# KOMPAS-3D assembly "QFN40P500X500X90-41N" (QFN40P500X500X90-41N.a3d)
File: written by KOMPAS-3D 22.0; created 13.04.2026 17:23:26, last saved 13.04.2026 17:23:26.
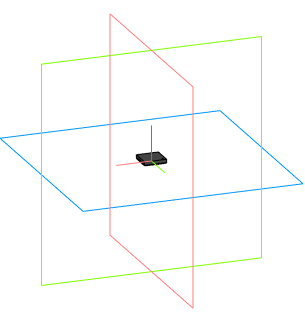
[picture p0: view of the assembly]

Document properties: Автор: Andrey; Полное имя файла: C:\Users\User1\Documents\QFN40P500X500X90-41N.a3d

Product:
- Component [detail]: RTL8211F-CG  | qty 1  | source file: RTL8211F-CG.m3d
- Part/product: QFN40P500X500X90-41N
    Комментарий: QFN40P500X500X90-41N

Expressions: QFN40P500X500X90-41N
Referenced files in C:\Users\User1\Documents\: RTL8211F-CG.m3d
